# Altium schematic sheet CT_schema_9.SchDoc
size 391 x 238 mm
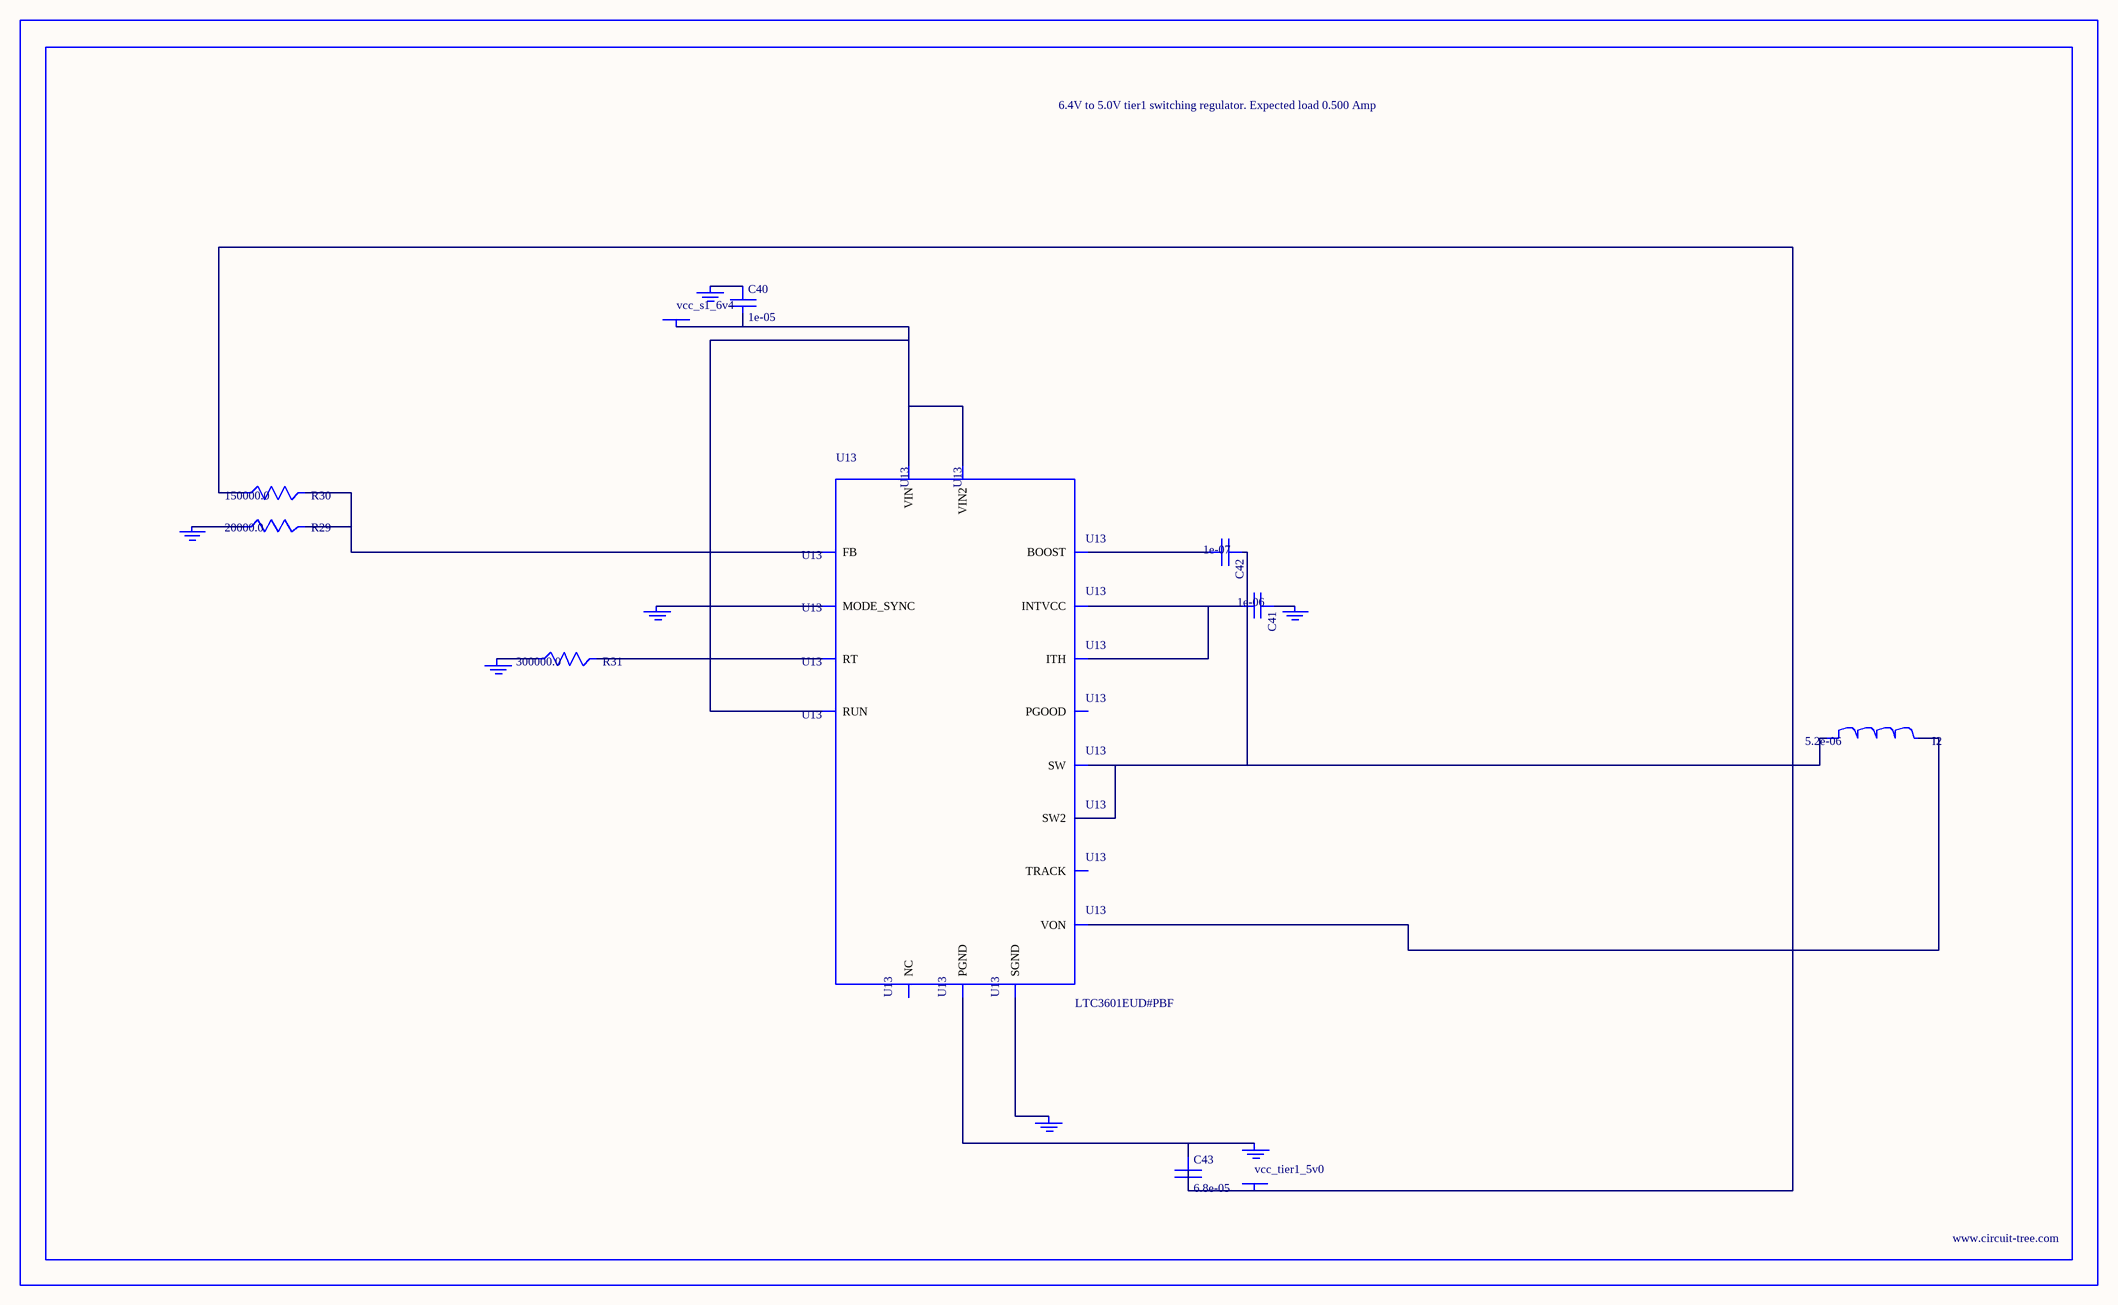
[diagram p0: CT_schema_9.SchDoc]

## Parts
BORDER8  (no value)
C40  1e-05  [C0805]
C41  1e-06  [C0603]
C42  1e-07  [C0402]
C43  6.8e-05  [2220]
GND_INSTANCE_8_0  (no value)
GND_INSTANCE_8_1  (no value)
GND_INSTANCE_8_2  (no value)
GND_INSTANCE_8_3  (no value)
GND_INSTANCE_8_4  (no value)
GND_INSTANCE_8_5  (no value)
GND_INSTANCE_8_6  (no value)
I2  5.2e-06  [DR1040]
POWER_INSTANCE_8_0  vcc_s1_6v4
POWER_INSTANCE_8_1  vcc_tier1_5v0
R29  20000.0  [R0603]
R30  150000.0  [R0603]
R31  300000.0  [R0603]
U13  LTC3601EUD#PBF  [QFN-16_EP]

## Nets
NetC40_1: C40.1 GND_INSTANCE_8_5.0(GND)
NetC40_2: C40.2 POWER_INSTANCE_8_0.0(PWR) U13.14(RUN) U13.15(VIN) U13.16(VIN2)
NetC41_1: C41.1 GND_INSTANCE_8_1.0(GND)
NetC41_2: C41.2 U13.7(INTVCC) U13.12(ITH)
NetC42_1: C42.1 I2.1 U13.3(SW) U13.4(SW2)
NetC42_2: C42.2 U13.6(BOOST)
NetC43_1: C43.1 GND_INSTANCE_8_6.0(GND) U13.17(PGND)
NetC43_2: C43.2 I2.2 POWER_INSTANCE_8_1.0(PWR) R30.1 U13.8(VON)
NetGND_INSTANCE_8_0_0: GND_INSTANCE_8_0.0(GND) U13.1(MODE_SYNC)
NetGND_INSTANCE_8_2_0: GND_INSTANCE_8_2.0(GND) U13.9(SGND)
NetGND_INSTANCE_8_3_0: GND_INSTANCE_8_3.0(GND) R31.1
NetGND_INSTANCE_8_4_0: GND_INSTANCE_8_4.0(GND) R29.1
NetR29_2: R29.2 R30.2 U13.11(FB)
NetR31_2: R31.2 U13.10(RT)

Not connected (* = marked no-connect by the designer): U13 2(PGOOD) 5(NC) 13(TRACK)

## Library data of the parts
BORDER8 = BORDER_PAGE8
C40 = C0805C106K8RACTU
C41 = C0603C105K3RACTU
C42 = C0402C104K3RACTU
C43 = C5750X5R1A686M
GND_INSTANCE_8_0-GND_INSTANCE_8_6 = GND
I2 = DR1040-5R2-R
POWER_INSTANCE_8_0 POWER_INSTANCE_8_1 = PWR
R29 = RC0603JR-0720KL
R30 = RC0603JR-07150KL
R31 = RC0603JR-07300KL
